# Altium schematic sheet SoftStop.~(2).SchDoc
size A
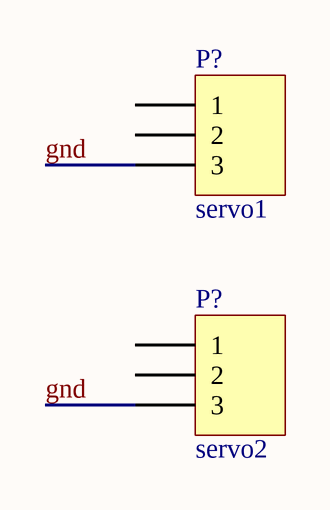
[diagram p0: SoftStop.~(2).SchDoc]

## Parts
(Parts that share a designator on the sheet are numbered #1, #2 ... from top to bottom, then left to right.)
P?#1  servo1  [HDR1X3H]
P?#2  servo2  [HDR1X3H]

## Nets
gnd: P?#1.3 P?#2.3

Not connected (* = marked no-connect by the designer): P?#1 1 2; P?#2 1 2

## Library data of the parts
P?#1 P?#2 = Header 3H: Header, 3-Pin, Right Angle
